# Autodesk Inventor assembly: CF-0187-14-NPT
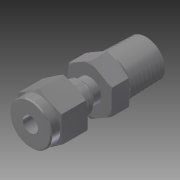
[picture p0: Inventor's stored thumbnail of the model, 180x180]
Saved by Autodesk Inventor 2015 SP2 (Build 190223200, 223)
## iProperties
Created: 2017-11
Part Number: CF-0187-14-NPT
Document SubType Name: Assembly
Designer: JN
Author: JN
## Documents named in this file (5)
- C:\Users\JN\Documents\CAD Drawings\The Sensor Connection\3D\CF\CF-0187-NPT\CF-0187-14-NPT.iam
- C:\Users\JN\Documents\CAD Drawings\The Sensor Connection\3D\CF\CF-0187-NPT\Imported Components\CF-0187-NPT Bottom Ferrule\CF-0187-NPT Bottom Ferrule.ipt
- C:\Users\JN\Documents\CAD Drawings\The Sensor Connection\3D\CF\CF-0187-NPT\Imported Components\CF-0187-NPT Cap\CF-0187-NPT Cap.ipt
- C:\Users\JN\Documents\CAD Drawings\The Sensor Connection\3D\CF\CF-0187-NPT\Imported Components\CF-0187-NPT Top Ferrule\CF-0187-NPT Top Ferrule.ipt
- C:\Users\JN\Documents\CAD Drawings\The Sensor Connection\3D\CF\CF-0187-NPT\Imported Components\CF-0187-14-NPT Threaded Body\CF-0187-14-NPT Threaded Body.ipt
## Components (4 placed, 4 different names)
1. CF-0187-NPT Bottom Ferrule:1 — Mate:4, Mate:8, Mate:9
2. CF-0187-NPT Cap:1 — Mate:5, Mate:6, Mate:7, Rotation:1
3. CF-0187-NPT Top Ferrule:1 — Mate:4, Mate:5, Mate:6, Mate:9
4. CF-0187-14-NPT Threaded Body:1 — Mate:7, Mate:8, Rotation:1
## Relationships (7: Mate 6, RelateRotation 1)
- Mate:4: CF-0187-NPT Bottom Ferrule:1 ↔ CF-0187-NPT Top Ferrule:1
- Mate:5: CF-0187-NPT Cap:1 ↔ CF-0187-NPT Top Ferrule:1
- Mate:6: CF-0187-NPT Cap:1 ↔ CF-0187-NPT Top Ferrule:1
- Mate:7: CF-0187-NPT Cap:1 ↔ CF-0187-14-NPT Threaded Body:1
- Mate:8: CF-0187-NPT Bottom Ferrule:1 ↔ CF-0187-14-NPT Threaded Body:1
- Rotation:1 [RelateRotation]: CF-0187-NPT Cap:1 ↔ CF-0187-14-NPT Threaded Body:1
- Mate:9: CF-0187-NPT Bottom Ferrule:1 ↔ CF-0187-NPT Top Ferrule:1
